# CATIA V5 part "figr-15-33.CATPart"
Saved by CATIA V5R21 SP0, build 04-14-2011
Part number: Part1
Bounding box of the stored display mesh (mm): x -40.264 to 42.014, y -25.445 to 25.445, z -51 to 0.75
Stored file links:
  D:\CATIA V5R21 E-RESOURCES\CATIA-V5R21\catia-v5r21-prt\c15-catia-v5r20-prt\c15-catia-v5r21-figr-15-33.CATPart
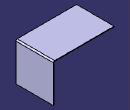
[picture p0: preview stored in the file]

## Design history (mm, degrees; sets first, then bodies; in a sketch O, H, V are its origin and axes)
SheetMetalParameters1: Thickness 0.75, BendRadius 1, KFactor 0.356492 {= log(min(100,max(20*SheetMetalParameters1.BendRadius,SheetMetalParameters1.Thickness)/SheetMetalParameters1.Thickness))/log(100)/2}, ReliefRadialLength 1, ReliefAxialLength 2, MinimumBendRadius 0
Body1 (main body)
  Sketch1 on xy-plane, origin (0, 0, 0), H (1, 0, 0), V (0, 1, 0)
    line L1 (-40.2643, 25.445) -> (40.2643, 25.445)
    line L2 (40.2643, 25.445) -> (40.2643, -25.445)
    line L3 (40.2643, -25.445) -> (-40.2643, -25.445)
    line L4 (-40.2643, -25.445) -> (-40.2643, 25.445)
    horizontal: L1 H, L3 H
    vertical: L2 V, L4 V
    symmetry: L1 L3 H, L4 L2 V
  Wall1: Thickness 0.75, Profile Sketch1
  Flange1: Guide edge [face of Wall1 | face of Wall1], Angle 90, KFacteur 0.356492 {= log(min(100,max(20*Flange1.Radius,SheetMetalParameters1.Thickness)/SheetMetalParameters1.Thickness))/log(100)/2}, Length 50, Radius 1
